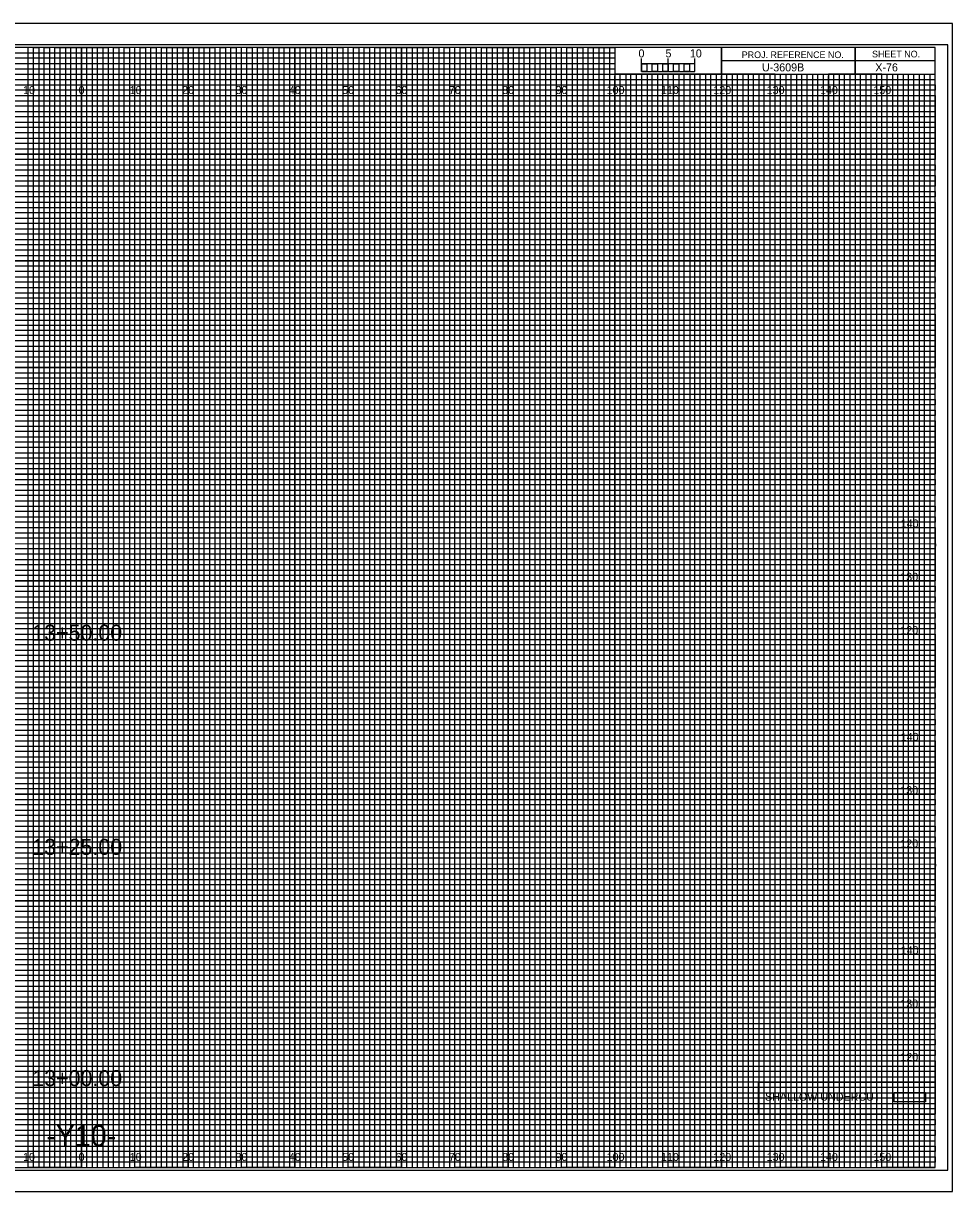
# Model space of a CAD drawing. Extents: x -13 to 323, y -5 to 654.
# Drawn here: x 149.1 to 323.3, y 435.5 to 654.5 of the extents above; entities that cross this region are included whole.
import ezdxf

# ---------------------------------------------------------------- set-up
doc = ezdxf.new("R2010")
doc.units = 0
for name, color, linetype in [('Prop DSN Text', 7, 'Continuous'), ('Prop Grid Mask', 7, 'Continuous'), ('Prop Road Plan_ Recs - UC Shallow (pattern)', 7, 'Continuous'), ('Prop XS Alignment Label', 7, 'Continuous'), ('Prop XS Bar Scale Labels', 7, 'Continuous'), ('Prop XS Elevation Labels', 7, 'Continuous'), ('Prop XS Offset Labels', 7, 'Continuous'), ('Prop XS Project Number', 7, 'Continuous'), ('Prop XS Sheet Number', 7, 'Continuous'), ('Prop XS Station Labels', 7, 'Continuous'), ('Sheet Cross Section CELL', 7, 'Continuous'), ('Sheet Cross Section Grid Major CELL', 7, 'Continuous'), ('Sheet Cross Section Grid Middle CELL', 7, 'Continuous'), ('Sheet Cross Section Grid Minor 1 CELL', 7, 'Continuous'), ('Sheet Cross Section Grid Minor 2 CELL', 7, 'Continuous'), ('Sheet Cross Section Scale CELL', 7, 'Continuous'), ('Sheet Cutting Line CELL', 7, 'Continuous'), ('Sheet DOT Grid CELL', 7, 'Continuous'), ('Sheet Plot Border Inside CELL', 7, 'Continuous'), ('Sheet Plot Border Outside CELL', 7, 'Continuous')]:
    doc.layers.add(name, color=color, linetype=linetype)

msp = doc.modelspace()

# ---------------------------------------------------------------- linework, layer by layer
at = {"layer": 'Prop Grid Mask'}
msp.add_lwpolyline([(286.89, 456.03), (320, 456.03), (320, 450), (286.89, 450)], close=True, dxfattribs=at)
at = {"layer": 'Prop Road Plan_ Recs - UC Shallow (pattern)'}
msp.add_lwpolyline([(312.34, 454.08), (318.23, 454.08), (318.23, 452.36), (312.34, 452.36)], close=True, dxfattribs=at)
at = {"layer": 'Sheet Cross Section CELL'}
for p, q in [((305, 650), (305, 645)), ((305, 645), (305, 650)), ((280, 647.5), (280, 645)), ((320, 647.49), (280, 647.49)), ((280, 645), (320, 645))]:
    msp.add_line(p, q, dxfattribs=at)
for points in [[(320, 650), (0, 650), (0, 440), (320, 440)], [(280, 650), (260, 650), (260, 645.03), (280, 645.03)], [(320, 650), (280, 650), (280, 645), (320, 645)]]:
    msp.add_lwpolyline(points, close=True, dxfattribs=at)
at = {"layer": 'Sheet Cross Section Grid Major CELL'}
for p, q in [((150, 650), (140, 650)), ((150, 440), (150, 650)), ((170, 650), (160, 650)), ((160, 650), (160, 440)), ((170, 440), (170, 650)), ((190, 650), (180, 650)), ((180, 650), (180, 440)), ((190, 440), (190, 650)), ((210, 650), (200, 650)), ((200, 650), (200, 440)), ((210, 440), (210, 650)), ((230, 650), (220, 650)), ((220, 650), (220, 440)), ((230, 440), (230, 650)), ((250, 650), (240, 650)), ((240, 650), (240, 440)), ((250, 440), (250, 650)), ((260, 650), (260, 440)), ((270, 440), (270, 645)), ((290, 645), (280, 645)), ((280, 645), (280, 440)), ((290, 440), (290, 645)), ((310, 645), (300, 645)), ((300, 645), (300, 440)), ((310, 440), (310, 645)), ((160, 440), (150, 440)), ((180, 440), (170, 440)), ((200, 440), (190, 440)), ((220, 440), (210, 440)), ((240, 440), (230, 440)), ((260, 440), (250, 440)), ((280, 440), (270, 440)), ((300, 440), (290, 440)), ((320, 440), (310, 440)), ((320, 440), (320, 440))]:
    msp.add_line(p, q, dxfattribs=at)
for points in [[(0, 640), (320, 640), (320, 630), (0, 630)], [(0, 620), (320, 620), (320, 610), (0, 610)], [(0, 600), (320, 600), (320, 590), (0, 590)], [(0, 580), (320, 580), (320, 570), (0, 570)], [(0, 560), (320, 560), (320, 550), (0, 550)], [(0, 540), (320, 540), (320, 530), (0, 530)], [(0, 520), (320, 520), (320, 510), (0, 510)], [(0, 500), (320, 500), (320, 490), (0, 490)], [(0, 480), (320, 480), (320, 470), (0, 470)], [(0, 460), (320, 460), (320, 450), (0, 450)]]:
    msp.add_lwpolyline(points, dxfattribs=at)
at = {"layer": 'Sheet Cross Section Grid Middle CELL'}
for points in [[(145, 440), (155, 440), (155, 650), (165, 650), (165, 440), (175, 440), (175, 650), (185, 650), (185, 440), (195, 440), (195, 650), (205, 650), (205, 440), (215, 440), (215, 650), (225, 650), (225, 440), (235, 440), (235, 650), (245, 650), (245, 440), (255, 440), (255, 650), (259.93, 650), (260, 650), (260, 645), (264.99, 645), (264.99, 440), (275, 440), (275, 645), (285, 645), (285, 440), (295, 440), (295, 645), (305, 645), (305, 440), (315, 440), (315, 645)], [(0, 645), (275, 645)], [(0, 625), (320, 625), (320, 635), (0, 635)], [(0, 605), (320, 605), (320, 615), (0, 615)], [(0, 585), (320, 585), (320, 595), (0, 595)], [(0, 565), (320, 565), (320, 575), (0, 575)], [(0, 545), (320, 545), (320, 555), (0, 555)], [(0, 525), (320, 525), (320, 535), (0, 535)], [(0, 505), (320, 505), (320, 515), (0, 515)], [(0, 485), (320, 485), (320, 495), (0, 495)], [(0, 465), (320, 465), (320, 475), (0, 475)], [(0, 445), (320, 445), (320, 455), (0, 455)]]:
    msp.add_lwpolyline(points, dxfattribs=at)
at = {"layer": 'Sheet Cross Section Grid Minor 1 CELL'}
for p, q in [((0, 649), (260, 649)), ((260, 649), (260, 647.98)), ((260, 647.98), (0, 647.98)), ((0, 647), (260, 647)), ((260, 647), (260, 645.89)), ((260, 645.89), (0, 645.89)), ((0, 644), (320, 644))]:
    msp.add_line(p, q, dxfattribs=at)
for points in [[(0, 643), (270, 643), (320, 643), (320, 642), (0, 642)], [(0, 641), (320, 641), (320, 639), (0, 639)], [(0, 638), (320, 638), (320, 637), (0, 636.98)], [(0, 636), (320, 636), (320, 634), (0, 634)], [(0, 633), (320, 633), (320, 632), (0, 632)], [(0, 631), (320, 631), (320, 629), (0, 629)], [(0, 628), (320, 628), (320, 627), (0, 627)], [(0, 626), (320, 626), (320, 624), (0, 624)], [(0, 623), (320, 623), (320, 622), (0, 622)], [(0, 621), (320, 621), (320, 619), (0, 619)], [(0, 618), (320, 618), (320, 617), (0, 617)], [(0, 616), (320, 616), (320, 613.95), (320, 613), (320, 612), (0, 612)], [(0, 614), (320, 614), (320, 613), (0, 613)], [(0, 611), (320, 611), (320, 609), (0, 609.03)], [(0, 609.03), (320, 609), (320, 608), (0, 608)], [(0, 607), (320, 607), (320, 606), (0, 606)], [(0, 604), (320, 604), (320, 603), (0, 603)], [(0, 602), (320, 602), (320, 601), (0, 601)], [(-0.07, 598.89), (320, 598.89), (320, 597.88), (-0.07, 597.88)], [(0, 597), (320, 597), (320, 596), (0, 596)], [(0, 594), (320, 594), (320, 593), (0, 593)], [(0, 592), (320, 592), (320, 591), (0, 591)], [(0, 589), (320, 589), (320, 588), (0, 588)], [(0, 587), (320, 587), (320, 586), (0, 586)], [(0, 584), (320, 584), (320, 583), (0, 583)], [(0, 582), (320, 582), (320, 581), (0, 581)], [(0, 579), (320, 579), (319.99, 577.98), (0, 578)], [(0, 577), (320, 577), (320, 576), (0, 576)], [(0, 574), (320, 574), (320, 573), (0, 573)], [(0, 572), (320, 572), (320, 571), (0, 571)], [(0, 569), (320, 569), (320, 568), (0, 568)], [(0, 567), (320, 567), (320, 566), (0, 566)], [(0, 564), (320, 564), (320, 563), (0, 563)], [(0, 562), (320, 562), (320, 561), (0, 561)], [(0, 559), (320, 559), (320, 558), (0, 558)], [(0, 556.99), (320.07, 556.91), (320, 556), (0, 556)], [(0, 554), (320, 554), (320, 553), (0, 553)], [(0, 552), (320, 552), (320, 551), (0, 551)], [(0, 549), (320, 549), (320, 548), (0, 548)], [(0, 547), (320, 547), (320, 546), (0, 546)], [(0, 544), (320, 544), (320, 543), (0, 543)], [(0, 542), (320, 542), (320, 541), (0, 541)], [(0, 539), (320, 539), (320, 538), (0, 538)], [(0, 537), (320, 537), (320, 536), (0, 536)], [(0, 534), (320, 534), (320, 533), (0, 533)], [(0, 532), (320, 532), (320, 531), (0, 531)], [(0, 529), (320, 529), (320, 528), (0, 528)], [(0, 527), (320, 527), (320, 526), (0, 526)], [(0, 524), (320, 524), (320, 523), (0, 523)], [(0, 522), (320, 522), (320, 521), (0, 521)], [(0, 519), (320, 519), (319.99, 517.98), (0, 518)], [(0, 517), (320, 517), (320, 516), (0, 516)], [(0, 514), (320, 514), (320, 513), (0, 513)], [(0, 512), (320, 512), (320, 511), (0, 511)], [(0, 509), (320, 509), (320, 508), (0, 508)], [(0, 507), (320, 507), (320, 506), (0, 506)], [(0, 504), (320, 504), (320, 503), (0, 503)], [(0, 502), (320, 502), (320, 501), (0, 501)], [(0, 499), (320, 499), (320, 498), (0, 498)], [(0, 496.99), (320.07, 496.91), (320, 496), (0, 496)], [(0, 494), (320, 494), (320, 493), (0, 493)], [(0, 492), (320, 492), (320, 491), (0, 491)], [(0, 489), (320, 489), (320, 488), (0, 488)], [(0, 487), (320, 487), (320, 486), (0, 486)], [(0, 484), (320, 484), (320, 483), (0, 483)], [(0, 482), (320, 482), (320, 481), (0, 481)], [(0, 479), (320, 479), (320, 478), (0, 478)], [(0, 477), (320, 477), (320, 476), (0, 476)], [(0, 474), (320, 474), (320, 473), (0, 473)], [(0, 472), (320, 472), (320, 471), (0, 471)], [(0, 469), (320, 469), (320, 468), (0, 468)], [(0, 467), (320, 467), (320, 466), (0, 466)], [(0, 464), (320, 464), (320, 463), (0, 463)], [(0, 462), (320, 462), (320, 461), (0, 461)], [(0, 459), (320, 459), (320, 458), (0, 458)], [(0, 457), (320, 457), (320, 456), (0, 456)], [(0, 454), (320, 454), (320, 453), (0, 453)], [(0, 452), (320, 452), (320, 451), (0, 451)], [(0, 449), (320, 449), (320, 448), (0, 448)], [(0, 447), (320, 447), (320, 446), (0, 446)], [(0, 444), (320, 444), (320, 443), (0, 443)], [(0, 442), (320, 442), (320, 441), (0, 441)]]:
    msp.add_lwpolyline(points, dxfattribs=at)
at = {"layer": 'Sheet Cross Section Grid Minor 2 CELL'}
for p, q in [((267, 645), (266.01, 645)), ((266.01, 645), (266.01, 440)), ((267, 440), (267, 645)), ((269, 645), (268, 645)), ((268, 645), (268, 440)), ((269, 440), (269, 645)), ((266.01, 440), (265, 440)), ((268, 440), (267, 440))]:
    msp.add_line(p, q, dxfattribs=at)
for points in [[(150, 440), (151, 440), (151, 650), (152, 650), (152, 440)], [(152, 440), (153, 440), (153, 650), (154, 650), (154, 440)], [(155, 440), (156, 440), (156, 650), (157, 650), (157, 440)], [(157, 440), (158, 440), (158, 650), (159, 650), (159, 440)], [(160, 440), (161, 440), (161, 650), (162, 650), (162, 440)], [(162, 440), (163, 440), (163, 650), (164, 650), (164, 440)], [(165, 440), (166, 440), (166, 650), (167, 650), (167, 440)], [(167, 440), (168, 440), (168, 650), (169, 650), (169, 440)], [(170, 440), (171, 440), (171, 650), (172, 650), (172, 440)], [(172, 440), (173, 440), (173, 650), (174, 650), (174, 440)], [(175, 440), (176, 440), (176, 650), (177, 650), (177, 440)], [(177, 440), (178, 440), (178, 650), (179, 650), (179, 440)], [(180, 440), (181, 440), (181, 650), (182, 650), (182, 440)], [(182, 440), (183, 440), (183, 650), (184, 650), (184, 440)], [(185, 440), (186, 440), (186, 650), (187, 650), (187, 440)], [(187, 440), (188, 440), (188, 650), (189, 650), (189, 440)], [(190, 440), (191, 440), (191, 650), (192, 650), (192, 440)], [(192, 440), (193, 440), (193, 650), (194, 650), (194, 440)], [(195, 440), (196, 440), (196, 650), (197, 650), (197, 440)], [(197, 440), (198, 440), (198, 650), (199, 650), (199, 440)], [(200, 440), (201, 440), (201, 650), (202, 650), (202, 440)], [(202, 440), (203, 440), (203, 650), (204, 650), (204, 440)], [(205, 440), (206, 440), (206, 650), (207, 650), (207, 440)], [(207, 440), (208, 440), (208, 650), (209, 650), (209, 440)], [(210, 440), (211, 440), (211, 650), (212, 650), (212, 440)], [(212, 440), (213, 440), (213, 650), (214, 650), (214, 440)], [(215, 440), (216, 440), (216, 650), (217, 650), (217, 440)], [(217, 440), (218, 440), (218, 650), (219, 650), (219, 440)], [(220, 440), (221, 440), (221, 650), (222, 650), (222, 440)], [(222, 440), (223, 440), (223, 650), (224, 650), (224, 440)], [(225, 440), (226, 440), (226, 650), (227, 650), (227, 440)], [(227, 440), (228, 440), (228, 650), (229, 650), (229, 440)], [(230, 440), (231, 440), (231, 650), (232, 650), (232, 440)], [(232, 440), (233, 440), (233, 650), (234, 650), (234, 440)], [(235, 440), (236, 440), (236, 650), (237, 650), (237, 440)], [(237, 440), (238, 440), (238, 650), (239, 650), (239, 440)], [(240, 440), (241, 440), (241, 650), (242, 650), (242, 440)], [(242, 440), (243, 440), (243, 650), (244, 650), (244, 440)], [(245, 440), (246, 440), (246, 650), (247, 650), (247, 440)], [(247, 440), (248, 440), (248, 650), (249, 650), (249, 440)], [(250, 440), (251, 440), (251, 650), (252, 650), (252, 440)], [(252, 440), (253, 440), (253, 650), (254, 650), (254, 440)], [(255, 440), (256, 440), (256, 650), (257, 650), (257, 440)], [(257, 440), (258, 440), (258, 650), (259, 650), (259, 440)], [(260, 440), (261, 440), (261, 645), (262.02, 645), (262.02, 440)], [(262, 440), (263, 440), (263, 645), (263.99, 645), (263.99, 440)], [(270, 440), (270.98, 440), (270.98, 645), (272, 645), (272, 440)], [(272, 440), (273, 440), (273, 645), (274.05, 645), (274.05, 440)], [(275, 440), (276, 440), (276, 645), (277, 645), (277, 440)], [(277, 440), (278, 440), (278, 645), (279, 645), (279, 440)], [(280, 440), (281, 440), (281, 645), (282, 645), (282, 440)], [(282, 440), (283, 440), (283, 645), (284, 645), (284, 440)], [(285, 440), (286, 440), (286, 645), (287, 645), (287, 440)], [(287, 440), (288, 440), (288, 645), (289, 645), (289, 440)], [(290, 440), (291, 440), (291, 645), (292, 645), (292, 440)], [(292, 440), (293, 440), (293, 645), (294, 645), (294, 440)], [(295, 440), (296, 440), (296, 645), (297, 645), (297, 440)], [(297, 440), (298, 440), (298, 645), (299, 645), (299, 440)], [(300, 440), (301, 440), (301, 645), (302, 645), (302, 440)], [(302, 440), (303, 440), (303, 645), (304, 645), (304, 440)], [(305, 440), (306, 440), (306, 645), (307, 645), (307, 440)], [(307, 440), (308, 440), (308, 645), (309, 645), (309, 440)], [(310, 440), (311, 440), (311, 645), (312, 645), (312, 440)], [(312, 440), (313, 440), (313, 645), (314, 645), (314, 440)], [(315, 440), (316, 440), (316, 645), (317, 645), (317, 440)], [(317, 440), (318, 440), (318, 645), (319, 645), (319, 440)]]:
    msp.add_lwpolyline(points, dxfattribs=at)
at = {"layer": 'Sheet Cross Section Scale CELL'}
for p, q in [((265, 645.49), (265, 647.9)), ((265, 646.9), (265, 647.9)), ((270, 645.49), (270, 647.9)), ((275, 645.49), (275, 647.9)), ((275, 646.9), (275, 647.9))]:
    msp.add_line(p, q, dxfattribs=at)
for points in [[(275, 646.9), (265, 646.9), (265, 645.49), (275, 645.49)], [(265, 646.9), (266, 646.9), (266, 645.49), (265, 645.49)], [(267, 646.9), (268, 646.9), (268, 645.49), (267, 645.49)], [(269, 646.9), (270, 646.9), (270, 645.49), (269, 645.49)], [(271, 646.9), (272, 646.9), (272, 645.49), (271, 645.49)], [(273, 646.9), (274, 646.9), (274, 645.49), (273, 645.49)]]:
    msp.add_lwpolyline(points, close=True, dxfattribs=at)
at = {"layer": 'Sheet Cutting Line CELL'}
for p, q in [((323.3, 654.5), (-13.4, 654.5)), ((-13.4, 435.5), (323.3, 435.5))]:
    msp.add_line(p, q, dxfattribs=at)
at = {"layer": 'Sheet DOT Grid CELL'}
for p, q in [((150, 440), (150, 650)), ((160, 440), (160, 650)), ((170, 440), (170, 650)), ((180, 440), (180, 650)), ((190, 440), (190, 650)), ((200, 440), (200, 650)), ((210, 440), (210, 650)), ((220, 440), (220, 650)), ((230, 440), (230, 650)), ((240, 440), (240, 650)), ((250, 440), (250, 650)), ((260, 440), (260, 644.69)), ((270, 440), (270, 644.69)), ((280, 440), (280, 644.69)), ((290, 440), (290, 644.69)), ((300, 440), (300, 644.69)), ((310, 440), (310, 644.69)), ((0, 640), (320, 640)), ((0, 630), (320, 630)), ((0, 620), (320, 620)), ((0, 610), (320, 610)), ((0, 600), (320, 600)), ((0, 590), (320, 590)), ((0, 580), (320, 580)), ((0, 570), (320, 570)), ((0, 560), (320, 560)), ((0, 550), (320, 550)), ((0, 540), (320, 540)), ((0, 530), (320, 530)), ((0, 520), (320, 520)), ((0, 510), (320, 510)), ((0, 500), (320, 500)), ((0, 490), (320, 490)), ((0, 480), (320, 480)), ((0, 470), (320, 470)), ((0, 460), (320, 460)), ((0, 450), (320, 450))]:
    msp.add_line(p, q, dxfattribs=at)
at = {"layer": 'Sheet Plot Border Inside CELL'}
msp.add_lwpolyline([(-10.8, 439.5), (322.4, 439.5), (322.4, 650.5), (-10.8, 650.5)], close=True, dxfattribs=at)
at = {"layer": 'Sheet Plot Border Outside CELL'}
msp.add_lwpolyline([(-13.4, 435.5), (323.3, 435.5), (323.3, 654.5), (-13.4, 654.5)], close=True, dxfattribs=at)

# ---------------------------------------------------------------- texts
at = {"layer": 'Prop DSN Text'}
msp.add_text('SHALLOW UNDERCUT', height=1.5, dxfattribs=at).set_placement((288.13, 452.55))
at = {"layer": 'Prop XS Alignment Label'}
msp.add_text('-Y10-', height=4, dxfattribs=at).set_placement((153.41, 444))
at = {"layer": 'Prop XS Bar Scale Labels'}
for s, p in [('5', (269.47, 648.12)), ('10', (274.04, 648.12))]:
    msp.add_text(s, height=1.5, dxfattribs=at).set_placement(p)
at = {"layer": 'Prop XS Elevation Labels'}
for s, p in [('140', (313.57, 560)), ('130', (313.49, 550)), ('120', (313.5, 540)), ('140', (313.57, 520)), ('130', (313.49, 510)), ('120', (313.5, 500)), ('140', (313.57, 480)), ('130', (313.49, 470)), ('120', (313.5, 460))]:
    msp.add_text(s, height=1.5, dxfattribs=at).set_placement(p)
at = {"layer": 'Prop XS Offset Labels'}
for s, p in [('10', (149.04, 641.25)), ('0', (159.45, 641.25)), ('0', (159.45, 641.25)), ('10', (169.04, 641.25)), ('20', (178.86, 641.25)), ('30', (188.86, 641.25)), ('40', (198.86, 641.25)), ('50', (208.86, 641.25)), ('60', (218.86, 641.25)), ('70', (228.86, 641.25)), ('80', (238.86, 641.25)), ('90', (248.86, 641.25)), ('100', (258.44, 641.25)), ('110', (268.62, 641.25)), ('120', (278.44, 641.25)), ('130', (288.44, 641.25)), ('140', (298.44, 641.25)), ('150', (308.44, 641.25)), ('10', (149.04, 441.25)), ('0', (159.45, 441.25)), ('0', (159.45, 441.25)), ('10', (169.04, 441.25)), ('20', (178.86, 441.25)), ('30', (188.86, 441.25)), ('40', (198.86, 441.25)), ('50', (208.86, 441.25)), ('60', (218.86, 441.25)), ('70', (228.86, 441.25)), ('80', (238.86, 441.25)), ('90', (248.86, 441.25)), ('100', (258.44, 441.25)), ('110', (268.62, 441.25)), ('120', (278.44, 441.25)), ('130', (288.44, 441.25)), ('140', (298.44, 441.25)), ('150', (308.44, 441.25))]:
    msp.add_text(s, height=1.5, dxfattribs=at).set_placement(p)
at = {"layer": 'Prop XS Project Number'}
msp.add_text('U-3609B', height=1.5, dxfattribs=at).set_placement((287.56, 645.5))
at = {"layer": 'Prop XS Sheet Number'}
msp.add_text('X-76', height=1.5, dxfattribs=at).set_placement((308.8, 645.5))
at = {"layer": 'Prop XS Station Labels'}
for s, p in [('13+50.00', (150.77, 538.78)), ('13+25.00', (150.77, 498.63)), ('13+00.00', (150.77, 455.28))]:
    msp.add_text(s, height=3, dxfattribs=at).set_placement(p)
at = {"layer": 'Sheet Cross Section CELL'}
for s, p in [('PROJ. REFERENCE NO.', (283.77, 647.99)), ('SHEET NO.', (308.19, 648.12))]:
    msp.add_text(s, height=1.25, dxfattribs=at).set_placement(p)
at = {"layer": 'Sheet Cross Section Scale CELL'}
msp.add_text('0', height=1.5, dxfattribs=at).set_placement((264.41, 648.12))

doc.saveas('drawing.dxf')
